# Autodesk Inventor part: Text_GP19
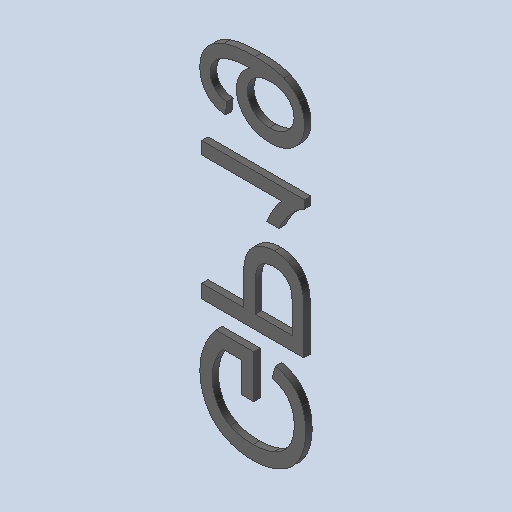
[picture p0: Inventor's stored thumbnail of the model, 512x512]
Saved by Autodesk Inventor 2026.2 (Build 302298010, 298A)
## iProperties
Created: 2026-10
Part Number: Text_GP19
Material: Générique
Document SubType Name: Modeling
Designer: mel
Density: 1 g/cm^3
Appearance: Par défaut
Author: mel
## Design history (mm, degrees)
feature "Base1"
feature "Base2"
feature "Base3"
feature "Base4"
node "Solide1"
node "Solide2"
node "Solide3"
node "Solide4"
